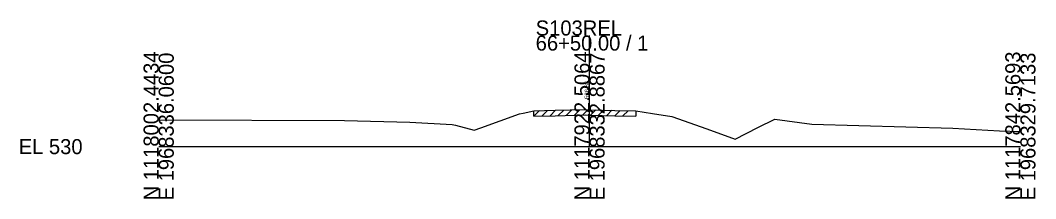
# Model space of a CAD drawing. Extents: x -26 to 163, y -10 to 24518.
# Drawn here: x -25.7 to 162.8, y 14990.3 to 15023.5 of the extents above; entities that cross this region are included whole.
import ezdxf

# ---------------------------------------------------------------- set-up
doc = ezdxf.new("R2010")
doc.units = 0
for name, color, linetype in [('RD_GPK_XS_Cell', 7, 'Continuous'), ('RD_XS_ExGround', 7, 'Continuous'), ('RD_XS_ExPaveRet', 7, 'Continuous'), ('RD_XS_TX_Elev_EX', 7, 'Continuous')]:
    doc.layers.add(name, color=color, linetype=linetype)

msp = doc.modelspace()

# ---------------------------------------------------------------- linework, layer by layer
at = {"layer": 'RD_GPK_XS_Cell'}
for p, q in [((80, 15000), (80, 15020.66)), ((0, 15000), (80, 15000)), ((80, 15000), (160, 15000))]:
    msp.add_line(p, q, dxfattribs=at)
at = {"layer": 'RD_XS_ExGround'}
msp.add_lwpolyline([(0, 15004.96), (34.48, 15004.85), (46.63, 15004.53), (54.47, 15004.14), (55.1, 15003.98), (58.58, 15003.05), (59.81, 15003.49), (67.01, 15006.08), (67.65, 15006.19), (69.68, 15006.66), (73.61, 15006.75), (79.19, 15006.89), (80, 15006.86), (84.7, 15006.74), (88.61, 15006.64), (91.7, 15006.17), (95.29, 15005.6), (101.78, 15003.3), (107.03, 15001.36), (111.24, 15003.56), (114.39, 15005.1), (121.27, 15004.16), (147.45, 15003.4), (156.14, 15002.96), (160, 15002.82)], dxfattribs=at)
at = {"layer": 'RD_XS_ExPaveRet'}
for p, q in [((69.68, 15005.66), (70.7, 15006.69)), ((69.68, 15005.66), (69.68, 15006.66)), ((69.68, 15005.66), (73.61, 15005.75)), ((71.18, 15005.7), (72.2, 15006.72)), ((72.68, 15005.73), (73.7, 15006.75)), ((73.61, 15005.75), (79.19, 15005.89)), ((74.18, 15005.77), (75.21, 15006.79)), ((75.68, 15005.8), (76.71, 15006.83)), ((77.18, 15005.84), (78.21, 15006.86)), ((78.68, 15005.87), (79.68, 15006.87)), ((79.19, 15005.89), (80, 15005.86)), ((80, 15005.86), (84.7, 15005.74)), ((80.18, 15005.86), (81.16, 15006.83)), ((81.68, 15005.82), (82.66, 15006.79)), ((83.18, 15005.78), (84.16, 15006.75)), ((84.68, 15005.74), (85.66, 15006.72)), ((84.7, 15005.74), (88.61, 15005.64)), ((86.18, 15005.7), (87.16, 15006.68)), ((88.61, 15006.64), (88.61, 15005.64))]:
    msp.add_line(p, q, dxfattribs=at)

# ---------------------------------------------------------------- texts
at = {"layer": 'RD_GPK_XS_Cell'}
for s, p in [('S103REL', (70, 15020.66)), ('66+50.00 / 1', (70, 15017.86)), ('EL 530', (-26, 14998.6))]:
    msp.add_text(s, height=2.8, dxfattribs=at).set_placement(p)
for s, p in [('N 1118002.4434', (0, 14990)), ('E 1968336.0600', (2.8, 14990)), ('N 1117922.5064', (80, 14990)), ('E 1968332.8867', (82.8, 14990)), ('N 1117842.5693', (160, 14990)), ('E 1968329.7133', (162.8, 14990))]:
    msp.add_text(s, height=2.8, rotation=90, dxfattribs=at).set_placement(p)
at = {"layer": 'RD_XS_TX_Elev_EX'}
msp.add_text('536.86', height=0.8, rotation=90, dxfattribs=at).set_placement((79.9, 15008.86))

doc.saveas('drawing.dxf')
